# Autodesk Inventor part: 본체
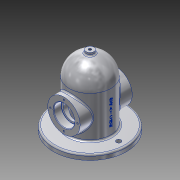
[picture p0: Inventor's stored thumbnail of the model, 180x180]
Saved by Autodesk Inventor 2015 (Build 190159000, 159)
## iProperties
Created: 2019-11
Part Number: 본체
Material: 알루미늄 6061
Document SubType Name: Modeling
Designer: Line503_02
Density: 2.7 g/cm^3
Appearance: 알루미늄 - 평지
Mass: 1106.12 g
Surface Area: 883.263 cm^2
Volume: 409.676 cm^3
Author: Line503_02
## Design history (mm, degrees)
sketch "스케치1"
  geometry: L1 (-40, 0)-(-40, -90); L2 (-40, -90)-(0, -90); L3 (0, 40)-(0, -90); A1 r 40 centre (0, 0) between (0, 40) and (-40, 0); 1 further point
  constraints: 6 end point, 2 point on circle, 2 vertical, 1 centre point, 1 coincident, 1 horizontal, 1 tangent
  dimensions: "d0" = 40 radius of A1; "d1" = 90 distance of L1.start L1.end; "d2" = 130 distance of L3.start L2.end
revolve "회전1" sketch "스케치1" stored, may be unused: angle "d3" = 90 deg
feature "쉘1" dims "d4" = 10
node "작업 평면1"
sketch "스케치2"
  geometry: L1 (40, -90)-(-40, -90) reference; C1 r 31 at (0, -40); 1 further point
  constraints: 1 centre point, 1 vertical alignment
  dimensions: "d6" = 62 diameter of C1; "d7" = 50 distance from line of L1 C1.centre
extrude "돌출1" join sketch "스케치2" stored distance "d8" = 10; taper "d9" = 0 deg
hole "구멍1" diameter "d12" = 33; stored, may be unused: countersink angle "d16" = 90 deg, drill point angle "d18" = 118 deg; dims "d10" = 10, "d11" = 10, "d13" = 6, "d14" = 40, "d15" = 15, "d17" = 8
sketch "스케치3"
  geometry: C1 r 20 at (0, 0) reference; 2 further points
  constraints: 1 horizontal alignment
  dimensions: "d19" = 26 distance of point (26, 0) C1.centre
hole "구멍2" sketch "스케치3" at (26, 0) diameter "d20" = 3.242; stored, may be unused: countersink angle "d24" = 90 deg, drill point angle "d26" = 118 deg; dims "d21" = 8, "d22" = 40, "d23" = 15, "d25" = 10
sketch "스케치4"
  geometry: C1 r 70 at (0, 0); C2 r 30 at (0, 0); C3 r 40 at (0, 0) reference; C4 r 30 at (0, 0) reference; C5 r 4.5 at (55, 0); C6 r 4.5 at (-55, 0); 1 further point
  constraints: 4 centre point, 2 coincident, 2 equal radius, 2 horizontal alignment
  dimensions: "d30" = 140 diameter of C1; "d31" = 9 diameter of C5; "d32" = 110 distance of C6.centre C5.centre; "d33" = 55 distance of point (0, 0) C5.centre (= 0.5 x d32)
extrude "돌출2" join sketch "스케치4" distance "d34" = 10; taper "d35" = 0 deg
node "작업 평면2"
sketch "스케치5"
  geometry: C1 r 7.5 at (0, 0); 1 further point
  constraints: 1 centre point, 1 coincident
  dimensions: "d37" = 15 diameter of C1
extrude "돌출3" join sketch "스케치5" stored distance "d38" = 10; taper "d39" = 0 deg
hole "구멍3" diameter "d42" = 5.188; stored, may be unused: countersink angle "d46" = 90 deg, drill point angle "d48" = 118 deg; dims "d40" = 10, "d41" = 10, "d43" = 12, "d44" = 40, "d45" = 15, "d47" = 16
fillet "모깎기1" dims "d49" = 3, "d50" = 0.3
chamfer "모따기1" distance "d51" = 1; stored, may be unused: second distance "d52" = 2, angle "d53" = 45 deg
node "작업 평면3"
sketch "스케치6"
  geometry: L1 (70, -45)-(-70, -45) reference; 2 further points
  constraints: 1 vertical alignment, 1 other
  dimensions: "d54" = 50 distance from line of point (0, 5) L1
feature "엠보싱1" sketch "스케치6" dims "d0" = 40, "d1" = 90, "d2" = 130, "d55" = 0.5, "d56" = 0
node "솔리드1"
pattern_circular "원형 패턴1" dims angle "d28" = 360 deg
mirror "대칭1"
other parameters: "d36" = -135
